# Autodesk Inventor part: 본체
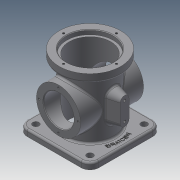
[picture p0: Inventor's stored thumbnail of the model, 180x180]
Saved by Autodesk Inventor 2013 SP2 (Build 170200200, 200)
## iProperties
Created: 2021-03
Part Number: 본체
Material: Generic
Document SubType Name: Modeling
Designer: kumcom13
Density: 1 g/cm^3
Mass: 311.967 g
Surface Area: 879.783 cm^2
Volume: 311.967 cm^3
Author: kumcom13
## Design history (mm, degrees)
sketch "스케치1"
  geometry: L1 (-57, 57)-(57, 57); L2 (57, 57)-(57, -57); L3 (57, -57)-(-57, -57); L4 (-57, -57)-(-57, 57); L5 (-57, 57)-(57, -57); L6 (57, 57)-(-57, -57); 1 further point
  constraints: 12 end point, 2 midpoint, 2 parallel, 1 horizontal, 1 perpendicular
  dimensions: "d0" = 114 distance of L2.end L3.end; "d1" = 114 distance of L1.end L2.end
extrude "돌출1" new body sketch "스케치1" distance "d2" = 10; taper "d3" = 0 deg
sketch "스케치2"
  geometry: C1 r 38 at (0, 0); 1 further point
  constraints: 1 centre point, 1 coincident
  dimensions: "d4" = 76 diameter of C1
extrude "돌출2" join sketch "스케치2" distance "d5" = 104; taper "d6" = 0 deg
sketch "스케치3"
  geometry: C1 r 38 at (0, 0) reference; C2 r 49 at (0, 0)
  constraints: 1 centre point, 1 coincident
  dimensions: "d7" = 98 diameter of C2
extrude "돌출3" join sketch "스케치3" distance "d8" = 13; taper "d9" = 0 deg
sketch "스케치4"
  geometry: C1 r 49 at (0, 0) reference; C2 r 37 at (0, 0)
  constraints: 1 centre point, 1 coincident
  dimensions: "d10" = 74 diameter of C2
extrude "돌출4" cut sketch "스케치4" distance "d11" = 7; taper "d12" = 0 deg
sketch "스케치5"
  geometry: C1 r 37 at (0, 0) reference; C2 r 33 at (0, 0)
  constraints: 1 centre point, 1 coincident
  dimensions: "d13" = 66 diameter of C2
extrude "돌출5" cut sketch "스케치5" stored distance "d14" = 7; taper "d15" = 0 deg
sketch "스케치6"
  geometry: L1 (0, 0)-(0, 42); C1 r 49 at (0, 0) reference; 1 further point
  constraints: 2 end point, 1 coincident, 1 vertical
  dimensions: "d16" = 42 distance of L1.start L1.end
hole "구멍1" sketch "스케치6" at (0, 42) diameter "d17" = 3.242; stored, may be unused: countersink angle "d21" = 90 deg, drill point angle "d23" = 118 deg; dims "d18" = 6, "d19" = 4, "d20" = 2, "d22" = 8
node "작업 평면1"
sketch "스케치7"
  geometry: L1 (0, 0)-(54, 0); C1 r 35 at (54, 0)
  constraints: 2 end point, 1 centre point, 1 coincident, 1 horizontal
  dimensions: "d28" = 54 distance of L1.start L1.end; "d29" = 70 diameter of C1
extrude "돌출6" join sketch "스케치7" stored distance "d30" = 7; taper "d31" = 0 deg
sketch "스케치8"
  geometry: L1 (0, 0)-(0, 31); C1 r 35 at (0, 0) reference; 2 further points
  constraints: 2 end point, 1 coincident, 1 vertical
  dimensions: "d32" = 31 distance of L1.start L1.end
hole "구멍2" sketch "스케치8" at (0, 31) diameter "d33" = 3.242; stored, may be unused: countersink angle "d37" = 90 deg, drill point angle "d39" = 118 deg; dims "d34" = 6, "d35" = 4, "d36" = 2, "d38" = 8
sketch "스케치9"
  geometry: C1 r 35 at (0, 0) reference; C2 r 24 at (0, 0); 1 further point
  constraints: 1 centre point, 1 coincident
  dimensions: "d43" = 48 diameter of C2
extrude "돌출7" cut sketch "스케치9" stored distance "d44" = 7; taper "d45" = 0 deg
fillet "모깎기1" dims "d46" = 14
sketch "스케치10"
  geometry: C1 r 5 at (43, 43); C2 r 5 at (-43, 43); C3 r 5 at (-43, -43); C4 r 5 at (43, -43); A1 r 14 centre (43, 43) between (57, 43) and (43, 57) reference; A2 r 14 centre (-43, 43) between (-43, 57) and (-57, 43) reference; A3 r 14 centre (-43, -43) between (-57, -43) and (-43, -57) reference; A4 r 14 centre (43, -43) between (43, -57) and (57, -43) reference
  constraints: 4 centre point, 4 coincident
  dimensions: "d47" = 10 diameter of C1; "d48" = 10 diameter of C2; "d49" = 10 diameter of C3; "d50" = 10 diameter of C4
extrude "돌출8" cut sketch "스케치10" stored distance "d51" = 7; taper "d52" = 0 deg
node "작업 평면2"
sketch "스케치11"
  geometry: L1 (0, 0)-(0, 54); L2 (0, 77)-(0, 77); L3 (7, 70)-(7, 41); L4 (0, 34)-(0, 34); L5 (-7, 41)-(-7, 70); L6 (7, 34)-(7, 54); L7 (7, 54)-(0, 54); A1 r 7 centre (0, 70) between (7, 70) and (0, 77); A2 r 7 centre (0, 70) between (0, 77) and (-7, 70); A3 r 7 centre (0, 41) between (-7, 41) and (0, 34); A4 r 7 centre (0, 41) between (0, 34) and (7, 41); 3 further points
  constraints: 14 end point, 9 point on line, 8 point on circle, 8 tangent, 4 centre point, 3 equal radius, 2 parallel, 2 perpendicular, 1 horizontal, 1 vertical
  dimensions: "d54" = 54 distance of L1.start L1.end; "d55" = 14 distance of L6.start point (-7, 34); "d56" = 43 distance of point (7, 77) L6.start; "d57" = 20 distance of L6.start L6.end; "d58" = 7 distance of L1.end L6.end; "d61" = 7 radius of A1
extrude "돌출9" join sketch "스케치11" stored distance "d59" = 7; taper "d60" = 15 deg
sketch "스케치12"
  geometry: A1 r 7 centre (0, 70) between (7, 70) and (-7, 70) reference; A2 r 7 centre (0, 41) between (-7, 41) and (7, 41) reference; 3 further points
  constraints: 2 coincident
hole "구멍3" sketch "스케치12" at (0, 70), (0, 41) diameter "d62" = 4.134; stored, may be unused: countersink angle "d66" = 90 deg, drill point angle "d68" = 118 deg; dims "d63" = 8, "d64" = 4, "d65" = 2, "d67" = 10
sketch "스케치13"
  geometry: C1 r 38 at (0, 0) reference; C2 r 50 at (0, 0)
  constraints: 1 centre point, 1 coincident, 1 other
  dimensions: "d69" = 100 diameter of C2
feature "엠보싱1" sketch "스케치13" dims "d0" = 114, "d1" = 114, "d70" = 0.5, "d71" = 0
chamfer "모따기1" distance "d72" = 1; stored, may be unused: second distance "d73" = 2, angle "d74" = 45 deg
fillet "모깎기2" dims "d75" = 3
fillet "모깎기3" dims "d76" = 3
node "솔리드1"
pattern_circular "원형 패턴1" dims angle "d25" = 360 deg
pattern_circular "원형 패턴2" dims angle "d41" = 360 deg
mirror "대칭1"
other parameters: "d53" = 55
